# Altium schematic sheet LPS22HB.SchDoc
size A
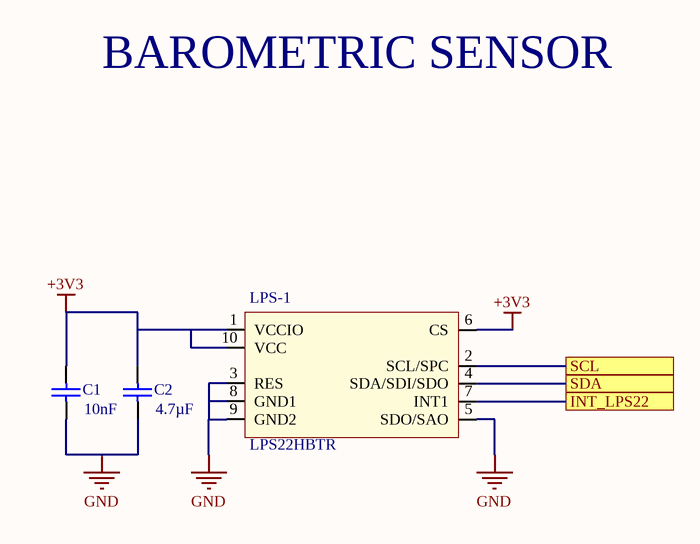
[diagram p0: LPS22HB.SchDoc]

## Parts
C1  value 10nF  [CAP-0402]  (hidden comment: C0402C103K3RACTU)
C2  value 4.7µF  [CAP-0402]  (hidden comment: GRM155R60J475ME47D)
LPS-1  LPS22HBTR  [LPS22H]

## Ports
INT_LPS22, SCL, SDA

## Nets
+3V3: C1.1 C2.2 LPS-1.1(VCCIO) LPS-1.6(CS) LPS-1.10(VCC)
GND: C1.2 C2.1 LPS-1.3(RES) LPS-1.5(SDO/SAO) LPS-1.8(GND1) LPS-1.9(GND2)
INT_LPS22: LPS-1.7(INT1) ; port INT_LPS22
SCL: LPS-1.2(SCL/SPC) ; port SCL
SDA: LPS-1.4(SDA/SDI/SDO) ; port SDA

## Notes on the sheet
- BAROMETRIC SENSOR

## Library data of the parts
C1 = C0008-A.3: CAP CHIP 0402 10nF 25V X7R 10%; Manufacturer: KEMET; Code Arduino: 0165
C2 = C0037-A.3: CAP CHIP 0402 4.7uF 6V3 X5R 20%; Manufacturer: Murata; Code Arduino: 0833; Voltage: 6.3V
LPS-1 = U0009-A.4: SENSOR PRESSURE 3.77 PSI ~ 18.27 PSI (26 kPa ~ 126 kPa) Absolute 24 b 10-WFLGA; Manufacturer: STMicroelectronics; Code Arduino: A5390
